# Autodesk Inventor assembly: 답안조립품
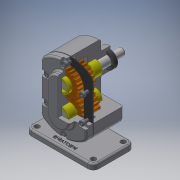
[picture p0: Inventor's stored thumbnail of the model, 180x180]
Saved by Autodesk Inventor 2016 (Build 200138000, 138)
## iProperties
Created: 2019-03
Part Number: 답안조립품
Document SubType Name: Assembly
Designer: Administrator
Author: Administrator
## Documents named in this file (11)
- C:\Users\Administrator\Desktop\490308V1004\답안조립품.iam
- C:\Users\Administrator\Desktop\490308V1004\본체.ipt
- C:\Users\Administrator\Desktop\490308V1004\메인축.ipt
- C:\Users\Administrator\Desktop\490308V1004\서브축.ipt
- C:\Users\Administrator\Desktop\490308V1004\키 6 x 6 x 18.ipt
- C:\Users\Administrator\Desktop\490308V1004\스퍼기어.ipt
- C:\Users\Administrator\Desktop\490308V1004\베어링부시.ipt
- C:\Users\Administrator\Desktop\490308V1004\볼트 M5.ipt
- C:\Users\Administrator\Desktop\490308V1004\오일 실 16 28 7.ipt
- C:\Users\Administrator\Desktop\490308V1004\커버.ipt
- C:\Users\Administrator\Desktop\490308V1004\개스킷.ipt
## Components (1 placed, 1 different names)
1. 개스킷:1
